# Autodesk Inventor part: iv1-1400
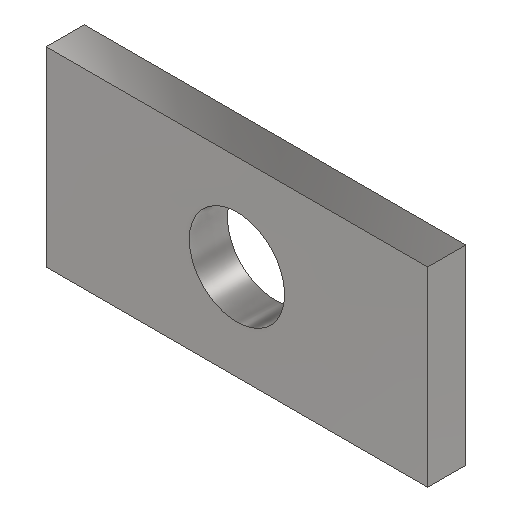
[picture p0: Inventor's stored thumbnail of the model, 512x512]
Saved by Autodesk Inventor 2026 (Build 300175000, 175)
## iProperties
Created: 2022-01
Part Number: iv1-1400
Material: Steel, Mild
Document SubType Name: Modeling
Designer: Lars Bertram Pedersen
Density: 7.85 g/cm^3
Appearance: Semi-Polished
Mass: 353.966 g
Surface Area: 128.037 cm^2
Volume: 45.0913 cm^3
Author: Lars Bertram Pedersen
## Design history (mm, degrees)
sketch "Sketch1"
  geometry: L1 (-50, -25)-(50, -25); L2 (50, -25)-(50, 25); L3 (50, 25)-(-50, 25); L4 (-50, 25)-(-50, -25); L5 (-50, -25)-(50, 25); L6 (50, -25)-(-50, 25); C1 r 12.5 at (0, 0); 1 further point
  constraints: 12 end point, 2 midpoint, 2 parallel, 1 centre point, 1 horizontal, 1 perpendicular
  dimensions: "Længden" = 100 distance of L2.end L3.end; "Bredde" = 50 distance of L1.end L2.end (= 0.5 x Længden); "d3" = 25 diameter of C1 (= 0.5 x Bredde); "hulafstand_x" = 50 distance from line of L2 C1.centre (= 0.5 x Længden); "Hulafstand_y" = 25 distance from line of C1.centre L1 (= 0.5 x Bredde)
extrude "Extrusion1" new body sketch "Sketch1" distance "Højde" = 10 (= 0.2 x Bredde); taper "Vinkel" = 0 deg
body "Solid1"
